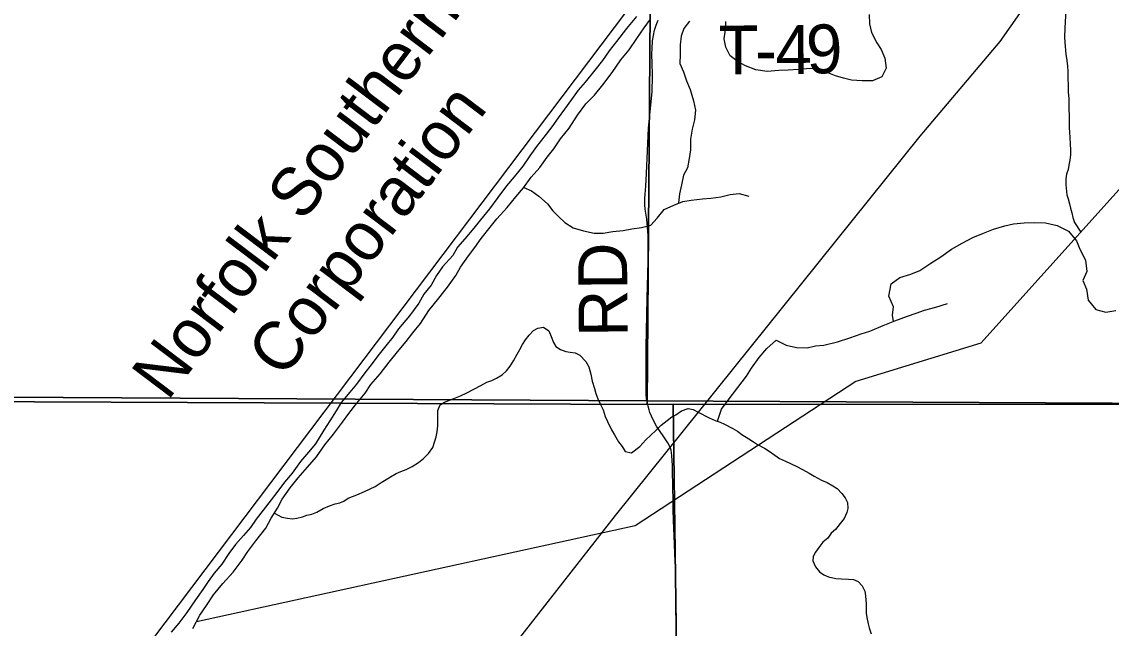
# Model space of a CAD drawing. Extents: x 0 to 34, y 0 to 22.
# Drawn here: x 6.195 to 7.463, y 15 to 15.706 of the extents above; entities that cross this region are included whole.
import ezdxf

# ---------------------------------------------------------------- set-up
doc = ezdxf.new("R2010")
doc.units = 0
for name, color, linetype in [('GM_X_Major_River', 7, 'Continuous'), ('GM_X_Minor_River', 7, 'Continuous'), ('GM_X_Rail_Line', 7, 'Continuous'), ('GM_X_Rail_Line_Text', 7, 'Continuous'), ('GM_X_Section', 7, 'Continuous'), ('GM_X_Township_Road', 7, 'Continuous'), ('GM_X_Township_Road_Text', 7, 'Continuous')]:
    doc.layers.add(name, color=color, linetype=linetype)

msp = doc.modelspace()

# ---------------------------------------------------------------- linework, layer by layer
at = {"layer": 'GM_X_Major_River'}
for points in [[(6.9105, 15.7117), (6.8988, 15.698), (6.8872, 15.6828), (6.8789, 15.6717), (6.871, 15.6607), (6.862, 15.6493), (6.8507, 15.6355), (6.8428, 15.626), (6.8349, 15.6153), (6.8267, 15.6039), (6.8195, 15.594), (6.812, 15.5834), (6.8026, 15.5715), (6.7943, 15.5605), (6.7864, 15.5495), (6.7782, 15.5377), (6.768, 15.5251), (6.7594, 15.5148), (6.7492, 15.5011), (6.7395, 15.4881), (6.7289, 15.4752), (6.721, 15.4656), (6.7109, 15.4531), (6.7022, 15.4432), (6.6966, 15.4337), (6.6849, 15.4203), (6.6778, 15.4104), (6.6714, 15.399), (6.6631, 15.3887), (6.6571, 15.3781), (6.6462, 15.3632), (6.6334, 15.3483), (6.6271, 15.3384), (6.6188, 15.3285), (6.6094, 15.3167), (6.6015, 15.3064), (6.5943, 15.2969), (6.5846, 15.284), (6.5767, 15.2744), (6.5669, 15.2626), (6.5609, 15.2527), (6.5534, 15.2413), (6.5466, 15.2303), (6.5369, 15.2143), (6.5286, 15.2048), (6.5196, 15.1937), (6.5098, 15.1804), (6.5008, 15.1697), (6.4929, 15.1594), (6.4853, 15.1491), (6.4759, 15.1373), (6.4677, 15.1267), (6.4613, 15.1171), (6.453, 15.1076), (6.4436, 15.0973), (6.4361, 15.0867), (6.4278, 15.0745), (6.4188, 15.0638), (6.412, 15.0543), (6.4056, 15.0448), (6.3974, 15.033), (6.3872, 15.0181), (6.3778, 15.0055), (6.3688, 14.9952)], [(6.3941, 14.9995), (6.4024, 15.0151), (6.4099, 15.0262), (6.4182, 15.0387), (6.4291, 15.0517), (6.4411, 15.065), (6.4516, 15.0791), (6.458, 15.089), (6.4674, 15.1016), (6.4791, 15.1161), (6.4854, 15.1279), (6.4926, 15.1397), (6.4982, 15.15), (6.5076, 15.1633), (6.5166, 15.1747), (6.5275, 15.1873), (6.5381, 15.1991), (6.5478, 15.2132), (6.558, 15.2258), (6.5685, 15.2395), (6.5757, 15.2498), (6.5851, 15.2619), (6.5948, 15.2734), (6.6012, 15.2833), (6.6121, 15.2959), (6.6227, 15.3096), (6.6324, 15.3214), (6.6426, 15.3336), (6.6501, 15.3435), (6.6591, 15.3545), (6.6689, 15.3694), (6.6806, 15.3839), (6.6907, 15.3968), (6.7001, 15.4105), (6.7057, 15.42), (6.7151, 15.4334), (6.7223, 15.4429), (6.7298, 15.4532), (6.7403, 15.4665), (6.7478, 15.4764), (6.7599, 15.4894), (6.77, 15.5019), (6.7791, 15.5122), (6.7881, 15.5248), (6.7982, 15.5362), (6.8065, 15.548), (6.8144, 15.5579), (6.8219, 15.5694), (6.8321, 15.5819), (6.8418, 15.5968), (6.8516, 15.6101), (6.8618, 15.6204), (6.8712, 15.6322), (6.8821, 15.6467), (6.8922, 15.6612), (6.902, 15.673), (6.911, 15.6863), (6.9196, 15.6985)], [(6.9196, 15.6985), (6.9268, 15.7088)]]:
    msp.add_lwpolyline(points, dxfattribs=at)
at = {"layer": 'GM_X_Minor_River'}
for points in [[(8.4344, 16.8906), (8.4339, 16.505), (8.1234, 16.2526), (7.7972, 15.8716), (7.3114, 15.3314), (7.166, 15.2871), (6.9088, 15.1189), (6.3982, 15.0073)], [(7.1812, 15.7143), (7.1816, 15.7033), (7.1842, 15.693), (7.1902, 15.6812), (7.1954, 15.6732), (7.1995, 15.6633), (7.201, 15.6516), (7.1961, 15.6417), (7.1851, 15.6369), (7.173, 15.6369), (7.1609, 15.6377), (7.1514, 15.6401), (7.142, 15.6428), (7.1326, 15.6466), (7.1224, 15.6501), (7.1129, 15.6512), (7.0989, 15.6502), (7.0872, 15.6495), (7.0762, 15.6488), (7.0626, 15.6477), (7.0494, 15.6497), (7.0373, 15.6543), (7.029, 15.6589), (7.0196, 15.6661), (7.0147, 15.676), (7.0125, 15.6859), (7.014, 15.6961), (7.0144, 15.706)], [(7.4101, 15.7191), (7.409, 15.6986), (7.4087, 15.6872), (7.4094, 15.6769), (7.4102, 15.6678), (7.4114, 15.6606), (7.4121, 15.6538), (7.4125, 15.6477), (7.4125, 15.6393), (7.4129, 15.6321), (7.4129, 15.6237), (7.4137, 15.6165), (7.4137, 15.604)], [(6.9721, 15.7062), (6.9656, 15.6979), (6.9626, 15.6888), (6.9614, 15.6789), (6.9613, 15.6675), (6.9609, 15.6569), (6.9654, 15.6474), (6.9688, 15.6368), (6.9729, 15.6269), (6.977, 15.6136), (6.9792, 15.6026), (6.9781, 15.5916), (6.9754, 15.5806), (6.9734, 15.5692), (6.9734, 15.5567), (6.9718, 15.5464), (6.9699, 15.5355), (6.9653, 15.5271), (6.963, 15.5158), (6.9607, 15.5055), (6.9595, 15.4949)], [(7.4137, 15.604), (7.4141, 15.5964), (7.4141, 15.5827), (7.4145, 15.5766), (7.4149, 15.5713), (7.4153, 15.5629), (7.4157, 15.5568), (7.4157, 15.5508), (7.4149, 15.5447), (7.4138, 15.5386), (7.4131, 15.5337), (7.4112, 15.5283), (7.4101, 15.523), (7.4101, 15.5158), (7.4116, 15.5044), (7.4131, 15.4995), (7.4146, 15.4938), (7.4158, 15.4888), (7.4173, 15.4831), (7.4184, 15.4778), (7.4204, 15.4721), (7.4278, 15.4609)], [(6.7794, 15.5127), (6.7883, 15.509), (6.797, 15.5025), (6.8068, 15.4937), (6.8132, 15.4857), (6.82, 15.4785), (6.8271, 15.472), (6.8369, 15.4659), (6.849, 15.4624), (6.8611, 15.4597), (6.8717, 15.4597), (6.883, 15.4615), (6.8951, 15.4626), (6.905, 15.4648), (6.9163, 15.4663), (6.9273, 15.4689), (6.9345, 15.4772), (6.9429, 15.487), (6.9539, 15.4923), (6.9645, 15.4964), (6.9743, 15.4979), (6.9875, 15.4997), (6.997, 15.5004), (7.0087, 15.5019), (7.0197, 15.5045), (7.0299, 15.5056), (7.0413, 15.5025)], [(7.2097, 15.3569), (7.2084, 15.364), (7.2095, 15.3738), (7.2041, 15.3863), (7.2071, 15.4008), (7.2172, 15.408), (7.2297, 15.4119), (7.2403, 15.4161), (7.2531, 15.4245), (7.2648, 15.4322), (7.2772, 15.441), (7.2897, 15.4479), (7.3021, 15.4544), (7.3146, 15.4597), (7.3259, 15.4644), (7.3391, 15.4682), (7.3493, 15.4705), (7.3618, 15.4717), (7.3732, 15.4722), (7.3864, 15.4715), (7.4, 15.4685), (7.4133, 15.4621), (7.4228, 15.4508), (7.4267, 15.4409), (7.4332, 15.428), (7.4347, 15.4151), (7.4302, 15.4045), (7.4345, 15.3943), (7.4364, 15.3818), (7.4452, 15.3708), (7.4569, 15.3678), (7.4686, 15.3694)], [(7.005, 15.2407), (7.0095, 15.2549), (7.0174, 15.2651), (7.0283, 15.28), (7.0385, 15.293), (7.0445, 15.3025), (7.0535, 15.3147), (7.0622, 15.3253), (7.0731, 15.3352), (7.0848, 15.3292), (7.0966, 15.3266), (7.1091, 15.3263), (7.1189, 15.3283), (7.1287, 15.3294), (7.1446, 15.3333), (7.1589, 15.3376), (7.1722, 15.3425), (7.182, 15.3456), (7.1975, 15.3522), (7.2114, 15.3575), (7.2258, 15.3629), (7.236, 15.3664), (7.2458, 15.3698), (7.259, 15.3733), (7.2726, 15.3776)], [(6.489, 15.1338), (6.4977, 15.1289), (6.5045, 15.1277), (6.5102, 15.127), (6.5151, 15.1277), (6.5219, 15.1296), (6.5268, 15.1315), (6.5325, 15.1326), (6.5386, 15.1349), (6.5458, 15.1391), (6.5533, 15.1421), (6.5598, 15.1447), (6.5651, 15.1459), (6.57, 15.1478), (6.5749, 15.1512), (6.5851, 15.155), (6.5938, 15.1591), (6.6063, 15.1648), (6.6135, 15.1694), (6.6192, 15.1728), (6.6241, 15.1758), (6.6309, 15.18), (6.6362, 15.1822), (6.6423, 15.1845), (6.6494, 15.1879), (6.6566, 15.1925), (6.6627, 15.1974), (6.6684, 15.2031), (6.6736, 15.2103), (6.6759, 15.2175), (6.6774, 15.2225), (6.6785, 15.2282), (6.6793, 15.2354), (6.6793, 15.2532), (6.6819, 15.2597), (6.6872, 15.2627), (6.6959, 15.2665), (6.7057, 15.2703), (6.7129, 15.2737), (6.7213, 15.2779), (6.7292, 15.2824), (6.7364, 15.2862), (6.7421, 15.2881), (6.7474, 15.2908), (6.7542, 15.2949), (6.7591, 15.2995), (6.7633, 15.3048), (6.7674, 15.3109), (6.7716, 15.3188), (6.7746, 15.3242), (6.778, 15.3302), (6.7814, 15.3355), (6.7855, 15.3409), (6.7905, 15.3465), (6.7958, 15.3492), (6.8022, 15.3503), (6.8083, 15.3461), (6.8113, 15.3393), (6.8139, 15.3324), (6.8166, 15.3275), (6.8219, 15.3241), (6.8284, 15.3218), (6.8333, 15.321), (6.839, 15.3202), (6.8446, 15.3176), (6.8515, 15.3103), (6.8549, 15.3039), (6.8572, 15.2955), (6.8591, 15.2875), (6.8617, 15.2788), (6.8633, 15.2731), (6.8655, 15.2666), (6.869, 15.2594), (6.8716, 15.2541), (6.8739, 15.2461), (6.8769, 15.2404), (6.8815, 15.2305), (6.8849, 15.2248), (6.8895, 15.2168), (6.894, 15.2111), (6.8974, 15.2054), (6.9046, 15.2039), (6.9145, 15.2114), (6.9213, 15.219), (6.9273, 15.2243), (6.933, 15.23), (6.9394, 15.2361), (6.9462, 15.2414), (6.9515, 15.246), (6.9564, 15.2482), (6.9629, 15.2528), (6.9708, 15.2554), (6.9765, 15.2543), (6.9822, 15.2512), (6.9951, 15.2448), (7.0019, 15.2417), (7.008, 15.2398), (7.0129, 15.2371), (7.0227, 15.2322)], [(7.0227, 15.2322), (7.028, 15.2291), (7.0333, 15.2253), (7.0413, 15.2204), (7.0466, 15.2169), (7.0515, 15.2135), (7.0595, 15.2093), (7.0648, 15.2059), (7.0716, 15.2013), (7.0769, 15.1975), (7.0838, 15.1941), (7.0898, 15.1914), (7.097, 15.188), (7.1038, 15.1845), (7.1114, 15.1803), (7.1175, 15.1769), (7.1258, 15.1723), (7.1323, 15.1693), (7.1391, 15.1655), (7.144, 15.1624), (7.1497, 15.1567), (7.1535, 15.1514), (7.1561, 15.1461), (7.1565, 15.1392), (7.1554, 15.1343), (7.1524, 15.1275), (7.1475, 15.1218), (7.1422, 15.1146), (7.1373, 15.1104), (7.1331, 15.1047), (7.1274, 15.0998), (7.1229, 15.0937), (7.1187, 15.0884), (7.1161, 15.0834), (7.1157, 15.0781), (7.1188, 15.0713), (7.1237, 15.0656), (7.1286, 15.0621), (7.1339, 15.0595), (7.1426, 15.0575), (7.1491, 15.0572), (7.1574, 15.0568), (7.1631, 15.0564), (7.1684, 15.0541), (7.1733, 15.0491), (7.1764, 15.0431), (7.1771, 15.0373), (7.1779, 15.0278), (7.1779, 15.0172), (7.1787, 15.0123), (7.1802, 15.005), (7.1814, 15.0001), (7.1836, 14.9933)]]:
    msp.add_lwpolyline(points, dxfattribs=at)
at = {"layer": 'GM_X_Rail_Line'}
for points in [[(6.4606, 14.1), (6.4571, 14.1954), (6.4477, 14.4405), (6.4524, 14.5081), (6.4637, 14.5568), (6.4857, 14.6083), (6.5473, 14.6979), (6.8861, 15.1309), (7.2406, 15.5724), (7.3338, 15.6825), (7.3851, 15.7562), (7.4225, 15.8224), (7.4495, 15.9132), (7.4686, 16.0084), (7.5816, 16.5648), (7.6436, 16.8869), (7.6684, 17.0095), (7.6975, 17.0913), (7.758, 17.2454), (8.0083, 17.8807), (8.1494, 18.2455), (8.2773, 18.5592), (8.2934, 18.6184), (8.454, 19.2815)], [(5.6775, 14.1), (5.8697, 14.3544), (7.0545, 15.9239), (7.071, 15.9465), (7.0887, 15.9728), (7.1081, 16.0024), (7.1344, 16.0471), (7.1632, 16.0963), (7.2298, 16.21), (7.4006, 16.5021), (7.517, 16.7007), (7.5541, 16.7664), (7.5716, 16.8015), (7.5902, 16.8448), (7.7573, 17.2724), (7.8518, 17.515)]]:
    msp.add_lwpolyline(points, dxfattribs=at)
at = {"layer": 'GM_X_Section'}
for points in [[(7.9341, 16.2671), (7.9294, 15.2601), (6.9531, 15.2604), (6.9228, 15.2602), (6.9303, 16.2282), (7.503, 16.2382)], [(6.9303, 16.2282), (6.9228, 15.2602), (5.7637, 15.2651), (5.7699, 16.2149)], [(6.9531, 15.2604), (6.9669, 14.2596), (5.7673, 14.2653), (5.7637, 15.2651), (6.9228, 15.2602)], [(6.9531, 15.2604), (7.9294, 15.2601), (7.9571, 15.2595), (7.9839, 14.2421), (6.9669, 14.2596)]]:
    msp.add_lwpolyline(points, close=True, dxfattribs=at)
at = {"layer": 'GM_X_Township_Road'}
for points in [[(5.7675, 15.2711), (6.9226, 15.2644), (7.9283, 15.2595), (7.9306, 15.7658), (7.9301, 16.1134), (7.9298, 16.2367), (7.9298, 16.2686), (7.9297, 16.3619), (7.9163, 17.252), (8.4218, 17.2637), (8.9, 17.2634), (8.9, 20.9)], [(6.923, 15.2629), (6.9228, 15.2638), (6.9223, 15.2663), (6.9217, 15.2727), (6.9217, 15.2804), (6.9217, 15.2882), (6.9217, 15.2941), (6.9217, 15.3021), (6.9217, 15.327), (6.9224, 15.3645), (6.9229, 15.3839), (6.9232, 15.398), (6.924, 15.4266), (6.924, 15.4452), (6.924, 15.4568), (6.9224, 15.476), (6.9208, 15.4876), (6.9204, 15.4924), (6.9204, 15.4966), (6.9203, 15.5001), (6.9206, 15.5049), (6.9212, 15.5143), (6.9221, 15.529), (6.9246, 15.5817), (6.9286, 15.6241), (6.9288, 15.6302), (6.9292, 15.6366), (6.9292, 15.6456), (6.9289, 15.6562), (6.9285, 15.6682), (6.9286, 15.6745), (6.9293, 15.6836), (6.9302, 15.6898), (6.9316, 15.6958), (6.9334, 15.7018), (6.9356, 15.7076)], [(6.9568, 14.9928), (6.9564, 15.0366), (6.9561, 15.0676), (6.956, 15.0707), (6.9555, 15.0769), (6.9542, 15.1076), (6.9539, 15.1157), (6.9536, 15.125), (6.9533, 15.138), (6.9532, 15.1454), (6.953, 15.167), (6.9526, 15.181), (6.9524, 15.1893), (6.9518, 15.201), (6.9509, 15.2069), (6.9493, 15.2114), (6.947, 15.2155), (6.9416, 15.2239), (6.9339, 15.2348), (6.9298, 15.2423), (6.9261, 15.2509), (6.9252, 15.2539), (6.924, 15.2581), (6.923, 15.2629)]]:
    msp.add_lwpolyline(points, dxfattribs=at)
msp.add_lwpolyline([(5.7705, 14.1), (8.9, 14.1), (8.9, 17.2634), (8.4218, 17.2637), (7.9163, 17.252), (7.9297, 16.3619), (7.9298, 16.2686), (7.9298, 16.2367), (7.9301, 16.1134), (7.9306, 15.7658), (7.9283, 15.2595), (6.9226, 15.2644), (5.7675, 15.2711), (5.7694, 14.855)], close=True, dxfattribs=at)

# ---------------------------------------------------------------- texts
at = {"layer": 'GM_X_Rail_Line_Text'}
for s, rotation, p in [('Norfolk Southern', 52.91, (6.3648, 15.2634)), ('Corporation', 52.8739, (6.4994, 15.289))]:
    msp.add_text(s, height=0.056629, rotation=rotation, dxfattribs=at).set_placement(p)
at = {"layer": 'GM_X_Township_Road_Text'}
for s, height, rotation, p in [('T', 0.0568, 0.0171, (7.006, 15.6445)), ('4', 0.0568, 0.6466, (7.0725, 15.6446)), ('9', 0.0568, 1.9576, (7.1089, 15.645)), ('-', 0.0568, 0.1594, (7.0486, 15.6445)), ('RD', 0.05682, 90.4814, (6.9003, 15.3391))]:
    msp.add_text(s, height=height, rotation=rotation, dxfattribs=at).set_placement(p)

doc.saveas('drawing.dxf')
